(* Logix 5000 project; controller TimeSyncExample vendor 1 type 14 code 96 rev 19.11; software revision 19.01 *)

TASK MainTask (continuous, watchdog 500 ms) : MainProgram

MODULES
   Local : vendor 1 type 14 code 96 (ICP 0, rev 19.11)
      Ethernet : vendor 1 type 12 code 200 (ICP 1, Ethernet 192.168.1.101, rev 3.1)
         TSM01 : ETHERNET-MODULE (Ethernet 192.168.1.225, rev 1.1, Output RPI 200 ms)
END_MODULES

TYPE AparianTimeSyncAccuracy :
STRUCT
   PDOP : REAL;
   HDOP : REAL;
   VDOP : REAL;
   LatitudeError : REAL;
   LongtitudeError : REAL;
   AltitudeError : REAL;
END_STRUCT
END_TYPE

TYPE AparianTimeSyncDateTime :
STRUCT
   UTC : LINT;
   Year : INT;
   Month : SINT;
   Day : SINT;
   Hour : SINT;
   Minute : SINT;
   Second : SINT;
   Nanosecond : DINT;
END_STRUCT
END_TYPE

TYPE AparianTimeSyncInput :
STRUCT
   Instance : STRING;
   Status : AparianTimeSyncStatusR02;
   InterferenceIndication : REAL;
   SatelliteCount : SINT;
   DateTime : AparianTimeSyncDateTime;
   Velocity : AparianTimeSyncVelocity;
   Position : AparianTimeSyncPosition;
   Odometer : AparianTimeSyncOdometer;
   Accuracy : AparianTimeSyncAccuracy;
END_STRUCT
END_TYPE

TYPE AparianTimeSyncOdometer :
STRUCT
   DistanceSinceReset : DINT;
   DistanceTotal : DINT;
   DistanceAccuracy : DINT;
END_STRUCT
END_TYPE

TYPE AparianTimeSyncOutput :
STRUCT
   ReferenceLatitude : REAL;
   ReferenceLongtitude : REAL;
   ReferenceAltitude : REAL;
END_STRUCT
END_TYPE

TYPE AparianTimeSyncPosition :
STRUCT
   Latitude : REAL;
   Longtitude : REAL;
   Altitude : REAL;
   ReferenceLatitude : REAL;
   ReferenceLongtitude : REAL;
   ReferenceAltitude : REAL;
   RelativeLatitude : REAL;
   RelativeLongtitude : REAL;
   RelativeAltitude : REAL;
   RelativeNorth : REAL;
   RelativeEast : REAL;
END_STRUCT
END_TYPE

TYPE AparianTimeSyncStatusR02 :
STRUCT
   ConfigurationValid : BOOL;
   PTPEnabled : BOOL;
   NTPEnabled : BOOL;
   AntennaShort : BOOL;
   Fix2D : BOOL;
   Fix3D : BOOL;
   FixAutonomous : BOOL;
   FixDifferential : BOOL;
   NTPSource1Connected : BOOL;
   NTPSource2Connected : BOOL;
END_STRUCT
END_TYPE

TYPE AparianTimeSyncVelocity :
STRUCT
   TrueCourseOverGround : REAL;
   SpeedOverGroundKnots : REAL;
   SpeedOverGroundKmh : REAL;
END_STRUCT
END_TYPE

VAR_GLOBAL   (* controller tags *)
   ResetOdometer : MESSAGE;
        MessageParameters(ServiceCode := 16#0076, ...)
   TimeSyncResetOdometer : BOOL;
   TSM01Input : AparianTimeSyncInput;
   TSM01Output : AparianTimeSyncOutput;
END_VAR

PROGRAM MainProgram   (* main routine MainRoutine *)

ROUTINE MainRoutine   (* ladder *)
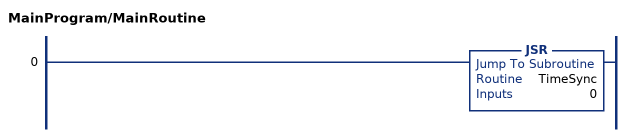
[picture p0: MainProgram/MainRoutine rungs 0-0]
   0: JSR(TimeSync,0);
END_ROUTINE

ROUTINE TimeSync   (* ladder *)
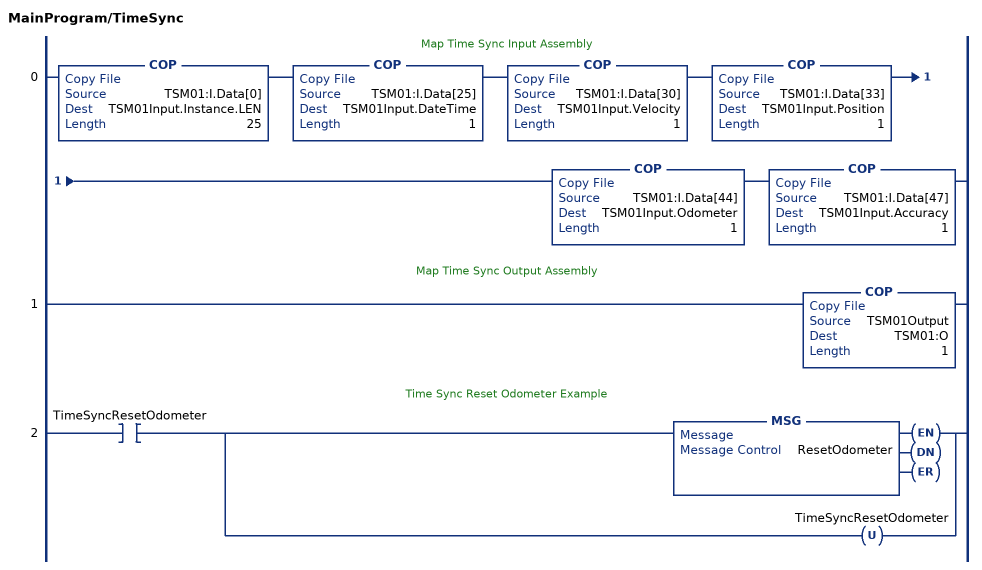
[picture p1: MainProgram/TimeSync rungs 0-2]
   // Map Time Sync Input Assembly
   0: COP(TSM01:I.Data[0],TSM01Input.Instance.LEN,25)COP(TSM01:I.Data[25],TSM01Input.DateTime,1)COP(TSM01:I.Data[30],TSM01Input.Velocity,1)COP(TSM01:I.Data[33],TSM01Input.Position,1)COP(TSM01:I.Data[44],TSM01Input.Odometer,1)COP(TSM01:I.Data[47],TSM01Input.Accuracy,1);
   // Map Time Sync Output Assembly
   1: COP(TSM01Output,TSM01:O,1);
   // Time Sync Reset Odometer Example
   2: XIC(TimeSyncResetOdometer)[MSG(ResetOdometer) ,OTU(TimeSyncResetOdometer) ];
END_ROUTINE
END_PROGRAM
